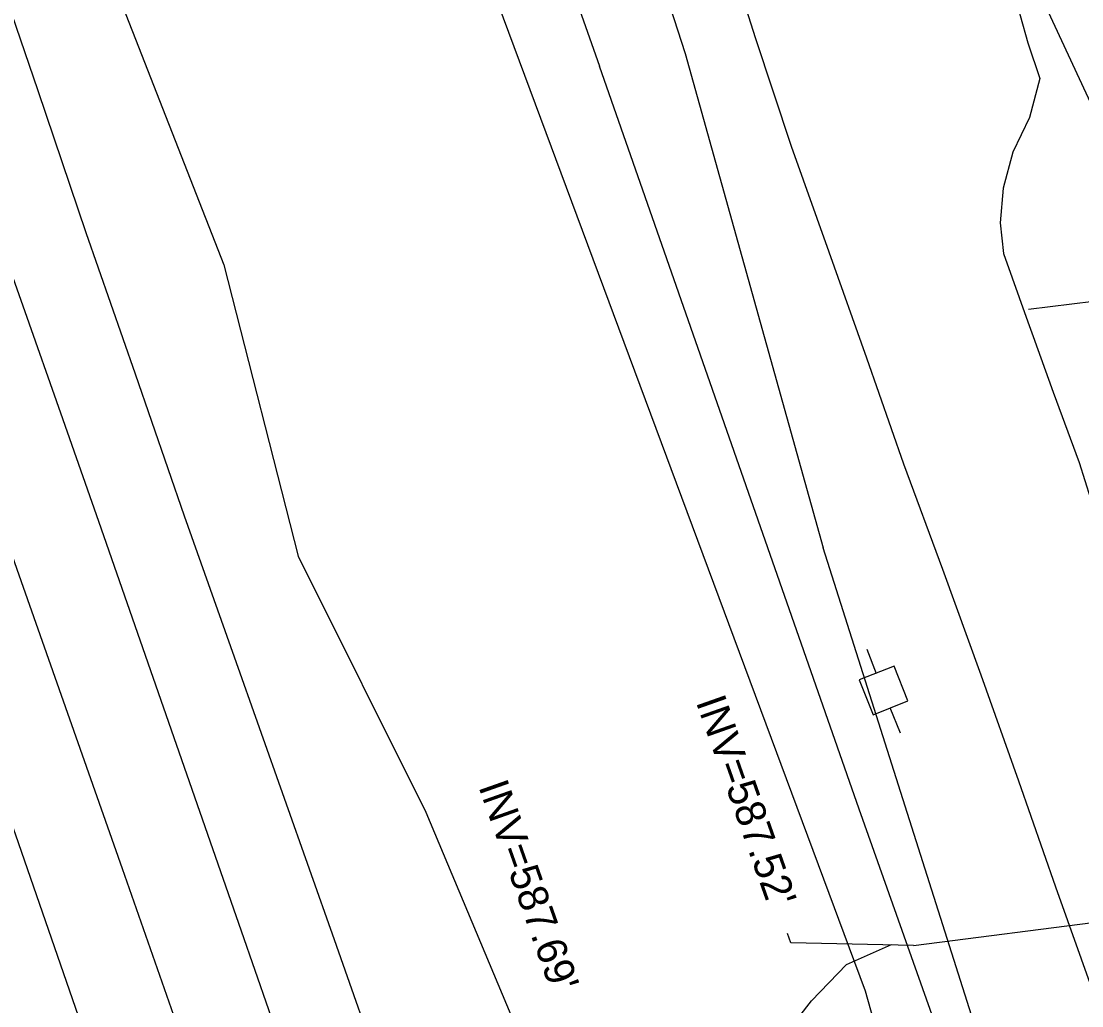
# Model space of a CAD drawing. Extents: x 2004847 to 2009016, y 1134161 to 1140101.
# Drawn here: x 2005197.7 to 2005339.3, y 1139280.7 to 1139412.1 of the extents above; entities that cross this region are included whole.
import ezdxf

# ---------------------------------------------------------------- set-up
doc = ezdxf.new("R2010")
doc.units = 0
for name, color, linetype in [('RD_EX_DR_Inlet_txCode', 7, 'Continuous'), ('RD_EX_DR_Pipe', 7, 'Continuous'), ('RD_EX_Driveway', 7, 'Continuous'), ('RD_EX_Fence_Other', 7, 'Continuous'), ('RD_EX_H2O', 7, 'Continuous'), ('RD_EX_Pavement_Markings', 7, 'Continuous'), ('RD_EX_Road', 7, 'Continuous'), ('RD_EX_UT', 7, 'Continuous'), ('RD_EX_VEG', 7, 'Continuous')]:
    doc.layers.add(name, color=color, linetype=linetype)

msp = doc.modelspace()

# ---------------------------------------------------------------- linework, layer by layer
at = {"layer": 'RD_EX_DR_Inlet_txCode'}
msp.add_lwpolyline([(2005316.81, 1139288.72), (2005300.44, 1139289.06), (2005300, 1139290.32)], dxfattribs=at)
at = {"layer": 'RD_EX_DR_Pipe'}
for p, q in [((2005310.05, 1139466.71), (2005374, 1139328.9)), ((2005316.81, 1139288.72), (2005378.35, 1139296.61))]:
    msp.add_line(p, q, dxfattribs=at)
at = {"layer": 'RD_EX_Driveway'}
msp.add_lwpolyline([(2005332.2, 1139373.67), (2005346.64, 1139375.48), (2005358.55, 1139351.44), (2005364.48, 1139353.18), (2005356.86, 1139377.67), (2005396.8, 1139382.64), (2005437.04, 1139385.06)], dxfattribs=at)
at = {"layer": 'RD_EX_Fence_Other'}
for points in [[(2005253.03, 1139716.13), (2005238.25, 1139668.78), (2005212.87, 1139585.21), (2005223.77, 1139551.44), (2005241.15, 1139501.52), (2005250.3, 1139475.87), (2005274.94, 1139406.13)], [(2005745.2, 1138077.7), (2005734.87, 1138106.23), (2005707.5, 1138183.28), (2005676.14, 1138273.06), (2005651.84, 1138341.76), (2005621.99, 1138424.97), (2005599.09, 1138488.22), (2005571.21, 1138570.22), (2005540.22, 1138656.02), (2005513.7, 1138731.21), (2005485.61, 1138810.48), (2005460.95, 1138877.54), (2005433.24, 1138957.41), (2005403.81, 1139043.22), (2005384.61, 1139099.04), (2005341.78, 1139216.01), (2005309.56, 1139306.93), (2005274.94, 1139406.13)]]:
    msp.add_lwpolyline(points, dxfattribs=at)
at = {"layer": 'RD_EX_H2O'}
for points in [[(2005258.13, 1139714.46), (2005253.87, 1139663.93), (2005250.08, 1139582.8), (2005251.51, 1139550.9), (2005257.79, 1139508.4), (2005263.59, 1139478.26), (2005286.37, 1139407.79), (2005304.78, 1139341.83)], [(2005471.87, 1138887.95), (2005471.87, 1138887.95), (2005442.96, 1138966.5), (2005417.56, 1139042.22), (2005389.59, 1139117.41), (2005362.32, 1139191.55), (2005330.8, 1139259.79), (2005304.78, 1139341.83)], [(2005291.14, 1139266.12), (2005297.52, 1139273.98), (2005303.22, 1139281.33), (2005307.87, 1139286.19), (2005313.88, 1139288.86)]]:
    msp.add_lwpolyline(points, dxfattribs=at)
at = {"layer": 'RD_EX_Pavement_Markings'}
for points in [[(2005099.8, 1139650.44), (2005104.99, 1139636.09), (2005110, 1139622.07), (2005119.39, 1139595.59), (2005124.35, 1139581.68), (2005129.53, 1139567.14), (2005134.71, 1139552.67), (2005144.07, 1139526.38), (2005153.34, 1139500.19), (2005158.57, 1139485.51), (2005163.37, 1139471.87), (2005168.32, 1139457.97), (2005187.56, 1139403.5), (2005198.22, 1139373.38), (2005202.99, 1139359.83), (2005208.05, 1139345.38), (2005227.11, 1139290.7), (2005236.22, 1139264.44)], [(2005089.62, 1139642.89), (2005104.01, 1139602.34), (2005118.25, 1139562.15), (2005129.1, 1139531.65), (2005143.47, 1139491.24), (2005157.78, 1139450.75), (2005168.68, 1139420.04), (2005183, 1139379.49), (2005197.17, 1139338.95), (2005211.23, 1139299), (2005221.78, 1139268.74), (2005235.83, 1139228.1), (2005249.98, 1139187.4), (2005260.51, 1139157.24), (2005274.62, 1139116.55), (2005288.65, 1139075.76), (2005302.47, 1139035.73), (2005313.02, 1139005.51), (2005327.03, 1138964.9)], [(2005079.57, 1139635.26), (2005103.99, 1139565.86), (2005118.52, 1139525.24), (2005132.81, 1139484.62), (2005147.14, 1139444.38), (2005157.91, 1139414.23), (2005172.33, 1139373.68), (2005186.55, 1139333.13), (2005197.31, 1139302.49), (2005211.39, 1139261.84), (2005225.48, 1139221.29), (2005236.15, 1139190.51), (2005250.29, 1139149.91), (2005264.43, 1139109.29), (2005278.35, 1139068.8), (2005288.92, 1139038.53), (2005302.87, 1138997.76), (2005316.8, 1138956.99)]]:
    msp.add_lwpolyline(points, dxfattribs=at)
at = {"layer": 'RD_EX_Road'}
for points in [[(2005112.41, 1139654.99), (2005119.15, 1139636.12), (2005125.86, 1139617.24), (2005132.55, 1139598.42), (2005139.26, 1139579.58), (2005146, 1139560.76), (2005148.28, 1139554.34), (2005154.39, 1139535.29), (2005160.59, 1139516.25), (2005167.58, 1139497.53), (2005173.83, 1139478.48), (2005180.35, 1139459.58), (2005186.96, 1139440.71), (2005193.46, 1139421.8), (2005199.94, 1139402.88), (2005206.35, 1139383.93), (2005212.95, 1139365.04), (2005219.47, 1139346.09), (2005226.17, 1139327.25), (2005232.81, 1139308.38), (2005239.49, 1139289.52), (2005246.15, 1139270.66)], [(2005262.05, 1139571.92), (2005263.04, 1139556.95), (2005264.31, 1139542.01), (2005266.06, 1139526.54), (2005268.13, 1139511.67), (2005270.82, 1139496.92), (2005274.38, 1139481.81), (2005278.26, 1139467.33), (2005282.36, 1139452.92), (2005286.71, 1139438.57), (2005291.18, 1139424.26), (2005295.68, 1139409.96), (2005300.52, 1139395.44), (2005305.55, 1139381.32), (2005310.58, 1139367.19), (2005315.51, 1139353.02), (2005320.72, 1139338.96), (2005325.8, 1139324.85), (2005330.86, 1139310.73), (2005335.77, 1139296.55), (2005340.82, 1139282.43)], [(2005330.05, 1139416.59), (2005332.09, 1139409.22), (2005333.68, 1139404.48), (2005332.31, 1139399.27), (2005330.11, 1139394.65), (2005328.8, 1139389.82), (2005328.42, 1139385.21), (2005328.83, 1139381.13), (2005332.08, 1139371.99), (2005332.79, 1139370.01), (2005335.48, 1139362.58), (2005338.95, 1139353.2), (2005341.96, 1139343.58)]]:
    msp.add_lwpolyline(points, dxfattribs=at)
at = {"layer": 'RD_EX_UT'}
for p, q in [((2005310.59, 1139328.27), (2005311.87, 1139325.05)), ((2005314.24, 1139326.03), (2005309.6, 1139324.18)), ((2005316.09, 1139321.39), (2005314.24, 1139326.03)), ((2005309.6, 1139324.18), (2005311.45, 1139319.54)), ((2005311.45, 1139319.54), (2005316.09, 1139321.39)), ((2005313.69, 1139320.51), (2005315.04, 1139317.12))]:
    msp.add_line(p, q, dxfattribs=at)
at = {"layer": 'RD_EX_VEG'}
for points in [[(2005330.5, 1139211.21), (2005310.44, 1139282.62), (2005250.29, 1139444.39), (2005204.89, 1139582.09), (2005214.9, 1139644.65), (2005219.77, 1139673.79), (2005232.04, 1139710.41)], [(2005125.25, 1139658.93), (2005151.45, 1139584.68), (2005175.06, 1139515.29), (2005196.19, 1139445.54), (2005210.11, 1139417.17), (2005224.77, 1139379.59), (2005234.72, 1139340.68), (2005251.74, 1139306.54), (2005266.92, 1139270.34), (2005298.91, 1139240.25), (2005311.38, 1139209.18), (2005326.22, 1139210.81)]]:
    msp.add_lwpolyline(points, dxfattribs=at)

# ---------------------------------------------------------------- texts
at = {"layer": 'RD_EX_DR_Inlet_txCode'}
for s, p in [("INV=587.52'", (2005287.75, 1139321.26)), ("INV=587.69'", (2005258.73, 1139309.95))]:
    msp.add_text(s, height=4, rotation=289.4494, dxfattribs=at).set_placement(p)

doc.saveas('drawing.dxf')
